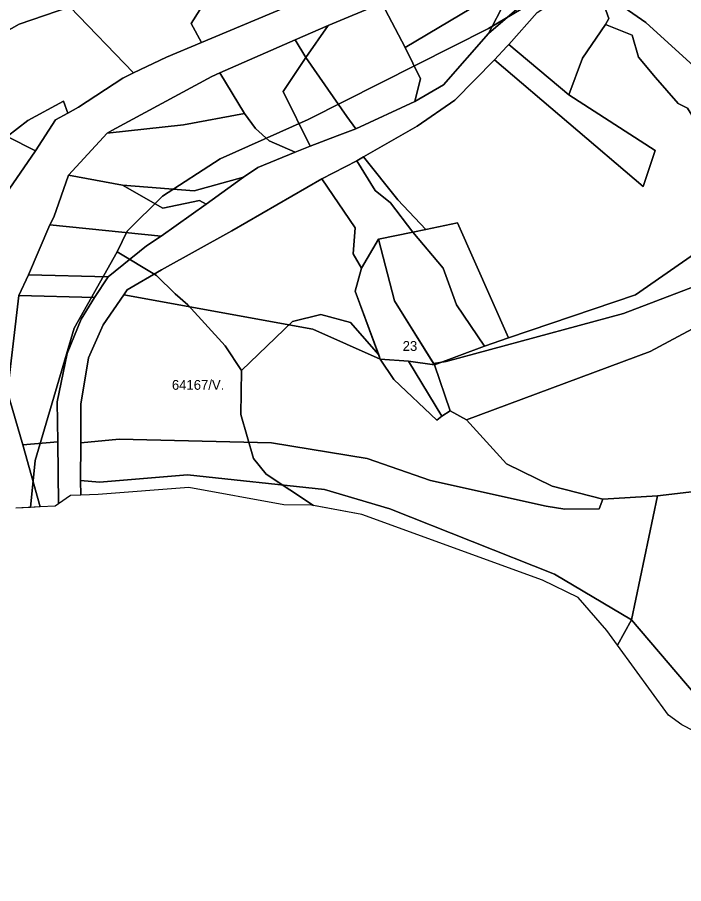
# Model space of a CAD drawing. Extents: x -521261 to -517465, y -1182764 to -1179456.
# Drawn here: x -519179 to -518838.8, y -1182502.4 to -1182060.3 of the extents above; entities that cross this region are included whole.
import ezdxf

# ---------------------------------------------------------------- set-up
doc = ezdxf.new("R2010")
doc.units = 0
for name, color, linetype in [('95560013', 7, 'Continuous'), ('95610013', 7, 'Continuous'), ('95620013', 7, 'Continuous'), ('95630013', 7, 'Continuous'), ('95640013', 7, 'Continuous'), ('95660013', 7, 'Continuous')]:
    doc.layers.add(name, color=color, linetype=linetype)

msp = doc.modelspace()

# ---------------------------------------------------------------- linework, layer by layer
at = {"layer": '95560013'}
for points in [[(-519032.35, -1181993.68), (-519023.89, -1181991.86), (-519005.47, -1181999.42), (-518974.73, -1182017.76), (-518969.43, -1182017.88), (-518980.58, -1182022.19), (-519014.12, -1182028.45), (-519004.74, -1182039.1), (-519035.76, -1182052.6), (-519084.93, -1182073.15), (-519090.2, -1182063.54), (-519052.86, -1182004.21)], [(-519071.99, -1182018.05), (-519052.86, -1182004.21), (-519090.2, -1182063.54), (-519084.93, -1182073.15), (-519102.81, -1182080.62), (-519119.74, -1182088.73), (-519152.16, -1182054.92), (-519144.87, -1182052.15), (-519120.85, -1182036.4), (-519105.37, -1182029.49), (-519087.95, -1182016.65)], [(-519178.02, -1182063.84), (-519152.16, -1182054.92), (-519119.74, -1182088.73), (-519125.18, -1182091.38), (-519147.86, -1182106.22), (-519153.26, -1182109.16), (-519155.39, -1182103.08), (-519173.6, -1182112.96), (-519184.26, -1182121.13), (-519207.36, -1182109.41), (-519202.24, -1182094.17), (-519208.47, -1182080.89)], [(-519153.26, -1182109.16), (-519159.6, -1182112.67), (-519169.74, -1182128.5), (-519184.26, -1182121.13), (-519173.6, -1182112.96), (-519155.39, -1182103.08)], [(-519222.19, -1182119.81), (-519207.36, -1182109.41), (-519191.55, -1182126.71), (-519184.26, -1182121.13), (-519169.74, -1182128.5), (-519183.14, -1182148.05), (-519185.65, -1182155.57), (-519198.46, -1182166.41), (-519238.23, -1182159.7), (-519244.72, -1182148.81), (-519243.51, -1182147.35), (-519233.52, -1182143.05)], [(-518810.55, -1182163.14), (-518784.05, -1182192.34), (-518855.87, -1182230.85), (-518949.78, -1182265.77), (-518957.97, -1182261.15), (-518966.08, -1182237.71), (-518940.53, -1182228.04), (-518928.17, -1182223.92), (-518863.4, -1182201.85), (-518825.45, -1182175.55)], [(-518784.05, -1182192.34), (-518780.9, -1182189.83), (-518778.49, -1182192.42), (-518761.94, -1182217.74), (-518753.86, -1182224.98), (-518730.33, -1182259.05), (-518705.7, -1182295.48), (-518754.91, -1182332.21), (-518785.58, -1182309.98), (-518799.71, -1182303), (-518817.23, -1182300.45), (-518852.15, -1182304.44), (-518880.01, -1182306.19), (-518905.94, -1182299.56), (-518929.3, -1182288.2), (-518949.78, -1182265.77), (-518855.87, -1182230.85)], [(-519135.17, -1182217.2), (-519124.68, -1182201.92), (-519028.21, -1182219.45), (-518993.75, -1182234.73), (-518986.74, -1182245.15), (-518964.8, -1182265.87), (-518962.22, -1182263.91), (-518957.97, -1182261.15), (-518949.78, -1182265.77), (-518929.3, -1182288.2), (-518905.94, -1182299.56), (-518880.01, -1182306.19), (-518881.99, -1182311.05), (-518899.52, -1182311.29), (-518908.97, -1182309.73), (-518968.09, -1182296.61), (-519000.43, -1182285.51), (-519049.24, -1182277.42), (-519126.97, -1182275.53), (-519146.65, -1182277.49), (-519146.62, -1182257.71), (-519142.62, -1182234.09)], [(-519049.24, -1182277.42), (-519000.43, -1182285.51), (-518968.09, -1182296.61), (-518908.97, -1182309.73), (-518899.52, -1182311.29), (-518881.99, -1182311.05), (-518880.01, -1182306.19), (-518852.15, -1182304.44), (-518865.37, -1182367.72), (-518904.79, -1182344.46), (-518988.83, -1182311.11), (-519022.28, -1182301.22), (-519092.07, -1182293.82), (-519137.06, -1182297.57), (-519146.71, -1182296.68), (-519146.65, -1182277.49), (-519126.97, -1182275.53)], [(-518799.71, -1182303), (-518785.58, -1182309.98), (-518754.91, -1182332.21), (-518753.1, -1182333.54), (-518708.42, -1182369.96), (-518648.65, -1182450.88), (-518612.29, -1182493.83), (-518656.41, -1182496.56), (-518685.18, -1182490.81), (-518725.77, -1182464.65), (-518828.06, -1182411.68), (-518865.37, -1182367.72), (-518852.15, -1182304.44), (-518817.23, -1182300.45)]]:
    msp.add_lwpolyline(points, close=True, dxfattribs=at)
at = {"layer": '95610013'}
for points in [[(-518762.93, -1181945.84), (-518735.59, -1181944.64), (-518720.24, -1181948.49), (-518709.38, -1181958.17), (-518725.01, -1181970.47), (-518741.93, -1181991.3), (-518793.08, -1182075.55), (-518798.87, -1182095.21), (-518803.83, -1182115.05), (-518829.83, -1182088.59), (-518858.12, -1182062.9), (-518889.08, -1182041.43), (-518875.98, -1182033.84), (-518827.3, -1181989.81), (-518772.88, -1181947.46)], [(-518943.48, -1182031.64), (-518930.34, -1182045.53), (-518980.94, -1182075.7), (-518992.91, -1182053.04)], [(-518895.94, -1182045.91), (-518889.08, -1182041.43), (-518880.73, -1182050.39), (-518876.94, -1182060.89), (-518878.76, -1182064.07), (-518890.47, -1182081.22), (-518897.42, -1182099.88), (-518928.06, -1182074.15), (-518913.53, -1182057.93)], [(-518930.34, -1182045.53), (-518930.08, -1182052.61), (-518938.53, -1182068.6), (-518961.45, -1182094.69), (-518976.16, -1182103.22), (-518974.22, -1182095.54), (-518973.1, -1182091.72), (-518980.94, -1182075.7)], [(-518865.04, -1182069.45), (-518861.95, -1182080.69), (-518853.17, -1182091.09), (-518841.68, -1182104.3), (-518836.85, -1182106.7), (-518830.45, -1182117.06), (-518823.16, -1182121.89), (-518821.12, -1182138.11), (-518825.45, -1182175.55), (-518863.4, -1182201.85), (-518928.17, -1182223.92), (-518954.27, -1182165.24), (-518970.44, -1182168.59), (-518984.8, -1182153.5), (-519002.24, -1182131.47), (-518974.87, -1182115.84), (-518955.62, -1182102.6), (-518935.43, -1182082.05), (-518859.47, -1182146.72), (-518853.31, -1182128.3), (-518897.42, -1182099.88), (-518890.47, -1182081.22), (-518878.76, -1182064.07)], [(-519031.78, -1182080.78), (-519043.25, -1182098.2), (-519029.51, -1182126.07), (-519037.12, -1182129.21), (-519050.51, -1182123.3), (-519057.37, -1182117.08), (-519062.98, -1182109.43), (-519075.61, -1182088.64), (-519037.14, -1182071.87)], [(-518929.02, -1182075.23), (-518928.06, -1182074.15), (-518897.42, -1182099.88), (-518853.31, -1182128.3), (-518859.47, -1182146.72), (-518935.43, -1182082.05)], [(-519031.78, -1182080.78), (-519010.79, -1182110.87), (-519006.27, -1182117.14), (-519015.68, -1182120.79), (-519029.51, -1182126.07), (-519043.25, -1182098.2)], [(-519079.71, -1182090.45), (-519075.61, -1182088.64), (-519062.98, -1182109.43), (-519094.26, -1182115.25), (-519133.19, -1182119.37), (-519130.79, -1182118.09)], [(-519062.98, -1182109.43), (-519057.37, -1182117.08), (-519050.51, -1182123.3), (-519037.12, -1182129.21), (-519056.16, -1182136.93), (-519063.58, -1182141.86), (-519088.81, -1182148.79), (-519125.38, -1182146.02), (-519152.93, -1182140.79), (-519133.19, -1182119.37), (-519094.26, -1182115.25)], [(-519023.49, -1182142.8), (-519005.68, -1182133.56), (-518996.41, -1182148.62), (-518988.52, -1182154.96), (-518977.1, -1182169.97), (-518994.67, -1182173.52), (-519003.38, -1182188.28), (-519007.49, -1182181.05), (-519006.56, -1182167.72)], [(-519005.68, -1182133.56), (-519002.24, -1182131.47), (-518984.8, -1182153.5), (-518970.44, -1182168.59), (-518977.1, -1182169.97), (-518988.52, -1182154.96), (-518996.41, -1182148.62)], [(-519152.93, -1182140.79), (-519125.38, -1182146.02), (-519104.8, -1182157.79), (-519086.02, -1182153.78), (-519082.7, -1182155.73), (-519105.61, -1182172.01), (-519162.51, -1182166.28), (-519160.42, -1182162.23)], [(-519063.58, -1182141.86), (-519082.7, -1182155.73), (-519086.02, -1182153.78), (-519104.8, -1182157.79), (-519125.38, -1182146.02), (-519088.81, -1182148.79)], [(-519006.56, -1182167.72), (-519007.49, -1182181.05), (-519003.38, -1182188.28), (-519006.59, -1182199.98), (-518993.75, -1182234.73), (-519028.21, -1182219.45), (-519124.68, -1182201.92), (-519122.96, -1182199.42), (-519105.49, -1182189.2), (-519069.53, -1182169.26), (-519023.49, -1182142.8)], [(-519162.51, -1182166.28), (-519105.61, -1182172.01), (-519113.15, -1182176.92), (-519132.61, -1182192.66), (-519173.29, -1182191.64)], [(-519173.29, -1182191.64), (-519132.61, -1182192.66), (-519139.61, -1182203.31), (-519178.27, -1182202.24)], [(-519178.27, -1182202.24), (-519139.61, -1182203.31), (-519146.38, -1182214.41), (-519153.61, -1182231.85), (-519158.67, -1182256.49), (-519158.44, -1182276.94), (-519176.17, -1182278.4), (-519184.01, -1182251.52)], [(-519176.17, -1182278.4), (-519158.44, -1182276.94), (-519158.09, -1182308.61), (-519159.7, -1182309.74), (-519167.38, -1182310.17)]]:
    msp.add_lwpolyline(points, close=True, dxfattribs=at)
at = {"layer": '95620013'}
for points in [[(-518994.67, -1182173.52), (-518986.47, -1182204.96), (-518966.08, -1182237.71), (-518979.39, -1182235.85), (-518993.75, -1182234.73), (-519006.59, -1182199.98), (-519003.38, -1182188.28)], [(-518979.39, -1182235.85), (-518962.22, -1182263.91), (-518964.8, -1182265.87), (-518986.74, -1182245.15), (-518993.75, -1182234.73)], [(-518966.08, -1182237.71), (-518957.97, -1182261.15), (-518962.22, -1182263.91), (-518979.39, -1182235.85)]]:
    msp.add_lwpolyline(points, close=True, dxfattribs=at)
at = {"layer": '95630013'}
msp.add_lwpolyline([(-519152.16, -1182054.92), (-519178.02, -1182063.84), (-519208.47, -1182080.89)], dxfattribs=at)
at = {"layer": '95640013'}
for points in [[(-518932.82, -1182025.58), (-518920.57, -1182037.37), (-518913.54, -1182039.67), (-518903.79, -1182038.57), (-518938.53, -1182068.6), (-518930.08, -1182052.61), (-518930.34, -1182045.53), (-518943.48, -1182031.64)], [(-518880.73, -1182050.39), (-518889.08, -1182041.43), (-518858.12, -1182062.9), (-518829.83, -1182088.59), (-518803.83, -1182115.05), (-518823.16, -1182121.89), (-518830.45, -1182117.06), (-518836.85, -1182106.7), (-518841.68, -1182104.3), (-518853.17, -1182091.09), (-518861.95, -1182080.69), (-518865.04, -1182069.45), (-518878.76, -1182064.07), (-518876.94, -1182060.89)], [(-519020.41, -1182064.46), (-518992.91, -1182053.04), (-518980.94, -1182075.7), (-518973.1, -1182091.72), (-518974.22, -1182095.54), (-518976.16, -1182103.22), (-519006.27, -1182117.14), (-519010.79, -1182110.87), (-519031.78, -1182080.78)], [(-519037.14, -1182071.87), (-519020.41, -1182064.46), (-519031.78, -1182080.78)], [(-518954.27, -1182165.24), (-518928.17, -1182223.92), (-518940.53, -1182228.04), (-518954.87, -1182206.98), (-518961.62, -1182188.34), (-518977.1, -1182169.97), (-518970.44, -1182168.59)], [(-518977.1, -1182169.97), (-518961.62, -1182188.34), (-518954.87, -1182206.98), (-518940.53, -1182228.04), (-518966.08, -1182237.71), (-518986.47, -1182204.96), (-518994.67, -1182173.52)], [(-519137.06, -1182297.57), (-519092.07, -1182293.82), (-519022.28, -1182301.22), (-518988.83, -1182311.11), (-518904.79, -1182344.46), (-518865.37, -1182367.72), (-518872.51, -1182380.67), (-518877.96, -1182373.17), (-518892.64, -1182356.33), (-518910.86, -1182347.51), (-519003.18, -1182314), (-519028.78, -1182309.33), (-519042.89, -1182309.05), (-519091.46, -1182300.2), (-519137.73, -1182303.79), (-519146.55, -1182304.08), (-519146.71, -1182296.68)], [(-518865.37, -1182367.72), (-518828.06, -1182411.68), (-518725.77, -1182464.65), (-518685.18, -1182490.81), (-518656.41, -1182496.56), (-518671.74, -1182502.4), (-518692.39, -1182498.07), (-518729.72, -1182477.4), (-518745.79, -1182462.67), (-518784.2, -1182442.1), (-518807.32, -1182438.02), (-518839.75, -1182421.31), (-518846.6, -1182416.39), (-518872.51, -1182380.67)]]:
    msp.add_lwpolyline(points, close=True, dxfattribs=at)
for points in [[(-518913.53, -1182057.93), (-518928.06, -1182074.15), (-518929.02, -1182075.23), (-518935.43, -1182082.05), (-518955.62, -1182102.6), (-518974.87, -1182115.84), (-519002.24, -1182131.47), (-519005.68, -1182133.56), (-519023.49, -1182142.8), (-519069.53, -1182169.26), (-519105.49, -1182189.2), (-519122.96, -1182199.42), (-519124.68, -1182201.92), (-519135.17, -1182217.2), (-519142.62, -1182234.09), (-519146.62, -1182257.71), (-519146.65, -1182277.49), (-519146.71, -1182296.68), (-519146.55, -1182304.08), (-519151.97, -1182304.35), (-519158.09, -1182308.61), (-519158.44, -1182276.94), (-519158.67, -1182256.49), (-519153.61, -1182231.85), (-519146.38, -1182214.41), (-519139.61, -1182203.31), (-519132.61, -1182192.66), (-519113.15, -1182176.92), (-519105.61, -1182172.01), (-519082.7, -1182155.73), (-519063.58, -1182141.86), (-519056.16, -1182136.93), (-519037.12, -1182129.21), (-519029.51, -1182126.07), (-519015.68, -1182120.79), (-519006.27, -1182117.14), (-518976.16, -1182103.22), (-518961.45, -1182094.69), (-518938.53, -1182068.6), (-518903.79, -1182038.57)], [(-518992.91, -1182053.04), (-519020.41, -1182064.46), (-519037.14, -1182071.87), (-519075.61, -1182088.64), (-519079.71, -1182090.45), (-519130.79, -1182118.09), (-519133.19, -1182119.37), (-519152.93, -1182140.79), (-519160.42, -1182162.23), (-519162.51, -1182166.28), (-519173.29, -1182191.64), (-519178.27, -1182202.24), (-519184.01, -1182251.52), (-519176.17, -1182278.4), (-519167.38, -1182310.17), (-519179.83, -1182310.84)], [(-519183.14, -1182148.05), (-519169.74, -1182128.5), (-519159.6, -1182112.67), (-519153.26, -1182109.16), (-519147.86, -1182106.22), (-519125.18, -1182091.38), (-519119.74, -1182088.73), (-519102.81, -1182080.62), (-519084.93, -1182073.15), (-519035.76, -1182052.6)]]:
    msp.add_lwpolyline(points, dxfattribs=at)
at = {"layer": '95660013'}
for points in [[(-518893, -1182039), (-518938.5, -1182066), (-519030.5, -1182112.5), (-519075.5, -1182132.5), (-519105, -1182151.5), (-519123, -1182169.5), (-519128, -1182180), (-519150, -1182219), (-519170, -1182286.5), (-519172.39, -1182310.44), (-519179.83, -1182310.84)], [(-518800, -1182185), (-518869.5, -1182211.5), (-518960, -1182236), (-518966.49, -1182237.05), (-518986.47, -1182204.96), (-518994.67, -1182173.52), (-519003.38, -1182188.28), (-519006.59, -1182199.98), (-518994.54, -1182232.58), (-519009, -1182216), (-519024, -1182212), (-519038.5, -1182215.5), (-519064.5, -1182240.5), (-519073, -1182228), (-519092, -1182207), (-519098.5, -1182201.5), (-519108, -1182192), (-519128, -1182180), (-519123, -1182169.5), (-519105, -1182151.5), (-519075.5, -1182132.5), (-519030.5, -1182112.5), (-518938.5, -1182066), (-518893, -1182039)], [(-518807.32, -1182438.02), (-518839.75, -1182421.31), (-518846.6, -1182416.39), (-518872.51, -1182380.67), (-518877.96, -1182373.17), (-518892.64, -1182356.33), (-518910.86, -1182347.51), (-519003.18, -1182314), (-519027.85, -1182309.5), (-519052, -1182293.5), (-519058.5, -1182285.5), (-519065, -1182263), (-519064.5, -1182240.5), (-519038.5, -1182215.5), (-519024, -1182212), (-519009, -1182216), (-518994.54, -1182232.58), (-518993.75, -1182234.73), (-518986.74, -1182245.15), (-518964.8, -1182265.87), (-518962.22, -1182263.91), (-518957.97, -1182261.15), (-518966.08, -1182237.71), (-518966.49, -1182237.05), (-518960, -1182236), (-518869.5, -1182211.5), (-518800, -1182185)]]:
    msp.add_lwpolyline(points, dxfattribs=at)
for points in [[(-518993.75, -1182234.73), (-518994.54, -1182232.58), (-519006.59, -1182199.98), (-519003.38, -1182188.28), (-518994.67, -1182173.52), (-518986.47, -1182204.96), (-518966.49, -1182237.05), (-518966.08, -1182237.71), (-518957.97, -1182261.15), (-518962.22, -1182263.91), (-518964.8, -1182265.87), (-518986.74, -1182245.15)], [(-519052, -1182293.5), (-519027.85, -1182309.5), (-519028.78, -1182309.33), (-519042.89, -1182309.05), (-519091.46, -1182300.2), (-519137.73, -1182303.79), (-519146.55, -1182304.08), (-519151.97, -1182304.35), (-519158.09, -1182308.61), (-519159.7, -1182309.74), (-519167.38, -1182310.17), (-519172.39, -1182310.44), (-519170, -1182286.5), (-519150, -1182219), (-519128, -1182180), (-519108, -1182192), (-519098.5, -1182201.5), (-519092, -1182207), (-519073, -1182228), (-519064.5, -1182240.5), (-519065, -1182263), (-519058.5, -1182285.5)]]:
    msp.add_lwpolyline(points, close=True, dxfattribs=at)

# ---------------------------------------------------------------- texts
msp.add_text('23', height=5, rotation=360, dxfattribs=at).set_placement((-518982.28, -1182230.53))
msp.add_text('64167/V.', height=5, dxfattribs=at).set_placement((-519100.12, -1182250.38))

doc.saveas('drawing.dxf')
